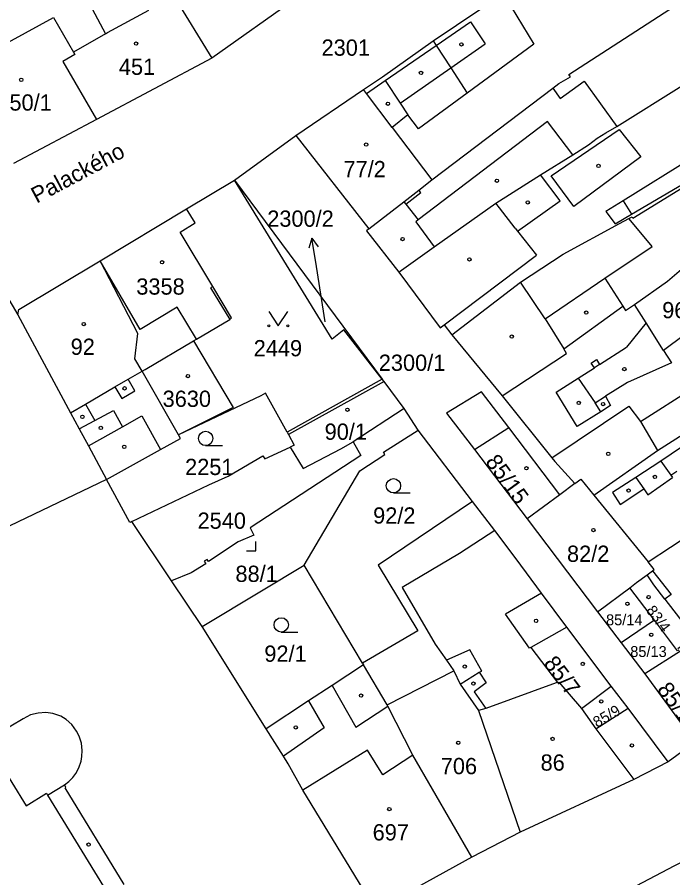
# Model space of a CAD drawing. Extents: x -679220 to -673243, y -1075091 to -1066557.
# Drawn here: x -676489.3 to -676420.8, y -1071759.5 to -1071669.5 of the extents above; entities that cross this region are included whole.
import ezdxf

# ---------------------------------------------------------------- set-up
doc = ezdxf.new("R2010")
doc.units = 0
for name, color, linetype in [('Hranice parcel', 7, 'Continuous'), ('Parcelní čísla', 7, 'Continuous'), ('Pop  PČ popisy', 7, 'Continuous'), ('Vnitřní kresba', 7, 'Continuous'), ('Značky budov', 7, 'Continuous'), ('Značky kultur', 7, 'Continuous')]:
    doc.layers.add(name, color=color, linetype=linetype)

msp = doc.modelspace()

# ---------------------------------------------------------------- linework, layer by layer
at = {"layer": 'Hranice parcel'}
for p, q in [((-676457.54, -1071665.6), (-676468.99, -1071673.74)), ((-676468.99, -1071673.74), (-676481.03, -1071680.16)), ((-676481.03, -1071680.16), (-676489.69, -1071684.74)), ((-676466.62, -1071686.49), (-676460.2, -1071681.83)), ((-676460.2, -1071681.83), (-676452.56, -1071691.6)), ((-676471.63, -1071689.48), (-676466.62, -1071686.49)), ((-676466.62, -1071686.49), (-676451.16, -1071707.32)), ((-676496.58, -1071688.3), (-676489.24, -1071700.57)), ((-676480.65, -1071694.94), (-676471.63, -1071689.48)), ((-676443.91, -1071702.66), (-676438.62, -1071709.04)), ((-676472.46, -1071713.12), (-676476.27, -1071706.46)), ((-676451.16, -1071707.32), (-676461.12, -1071712.84)), ((-676448.89, -1071710.38), (-676454.22, -1071713.88)), ((-676447.41, -1071712.65), (-676448.89, -1071710.38)), ((-676441.73, -1071720.1), (-676447.41, -1071712.65)), ((-676479.98, -1071717.8), (-676490.96, -1071723.08)), ((-676431.05, -1071718.24), (-676432.6, -1071719.4)), ((-676432.6, -1071719.4), (-676436.03, -1071721.91)), ((-676429.04, -1071719.44), (-676423.39, -1071726.4)), ((-676439.41, -1071723.14), (-676441.73, -1071720.1)), ((-676436.03, -1071721.91), (-676428.68, -1071731.63)), ((-676423.39, -1071726.4), (-676416.55, -1071721.95)), ((-676473.2, -1071728.4), (-676477.35, -1071722.21)), ((-676453.24, -1071737.03), (-676459.33, -1071726.76)), ((-676422.92, -1071727.36), (-676420.97, -1071729.84)), ((-676469.99, -1071733.18), (-676473.2, -1071728.4)), ((-676428.68, -1071731.63), (-676425.31, -1071729.15)), ((-676422.7, -1071732.52), (-676425.31, -1071729.15)), ((-676428.68, -1071731.63), (-676426.21, -1071734.89)), ((-676422.7, -1071732.52), (-676426.21, -1071734.89)), ((-676463.3, -1071743.87), (-676469.99, -1071733.18)), ((-676427.23, -1071739.43), (-676431.88, -1071733.26)), ((-676426.21, -1071734.89), (-676423.74, -1071738.14)), ((-676420, -1071735.76), (-676423.74, -1071738.14)), ((-676453.24, -1071737.03), (-676453.14, -1071737.2)), ((-676430.35, -1071741.77), (-676427.23, -1071739.43)), ((-676425.48, -1071741.71), (-676427.23, -1071739.43)), ((-676421.27, -1071747.32), (-676425.48, -1071741.71)), ((-676418.96, -1071745.63), (-676421.27, -1071747.32)), ((-676436.77, -1071754.7), (-676441.8, -1071757.31))]:
    msp.add_line(p, q, dxfattribs=at)
for points in [[(-676445.83, -1071671.91), (-676438.53, -1071666.96), (-676428.58, -1071660.59), (-676428.65, -1071660.49), (-676422.55, -1071656.64), (-676422.48, -1071656.74), (-676416.58, -1071652.94), (-676410.37, -1071648.97)], [(-676445.98, -1071686.46), (-676433.35, -1071676.88), (-676432.72, -1071676.4), (-676431.51, -1071675.68), (-676431.67, -1071675.43), (-676411.26, -1071662.18), (-676404.88, -1071658.28)], [(-676484.8, -1071662.19), (-676483.34, -1071664.69), (-676483.56, -1071664.81), (-676482.57, -1071666.51), (-676480.1, -1071671.18), (-676483.43, -1071673.12), (-676483.3, -1071673.35), (-676484.55, -1071674.07), (-676481.03, -1071680.16)], [(-676475.33, -1071663.38), (-676472.93, -1071667.3), (-676468.99, -1071673.74)], [(-676449.45, -1071696.12), (-676449.16, -1071695.9), (-676445.73, -1071693.47), (-676439.3, -1071688.9), (-676434.63, -1071685.95), (-676431.25, -1071683.83), (-676429.61, -1071682.8), (-676428.7, -1071682.09), (-676427.79, -1071681.54), (-676426.64, -1071680.89), (-676419.86, -1071676.64), (-676407.57, -1071668.83), (-676400.92, -1071664.77)], [(-676443.91, -1071702.66), (-676436.71, -1071697.18), (-676432.26, -1071694.25), (-676426.37, -1071691.03), (-676425.39, -1071690.51), (-676425.06, -1071690.34), (-676424.98, -1071690.46), (-676415.31, -1071684.52), (-676413.94, -1071683.68), (-676414.36, -1071683.06), (-676403.27, -1071675.59), (-676403.19, -1071675.52), (-676396.92, -1071671.69)], [(-676460.2, -1071681.83), (-676453.12, -1071677), (-676451.13, -1071675.67), (-676445.83, -1071671.91)], [(-676445.83, -1071671.91), (-676445.52, -1071672.4), (-676444.01, -1071674.75), (-676442.31, -1071677.4), (-676447.38, -1071681.13), (-676448.5, -1071679.66), (-676450.13, -1071680.97), (-676445.98, -1071686.46)], [(-676451.16, -1071707.32), (-676455.19, -1071702.14), (-676456.4, -1071703.12), (-676466.62, -1071686.49)], [(-676452.56, -1071691.6), (-676448.91, -1071688.75), (-676447.35, -1071687.53), (-676445.98, -1071686.46)], [(-676470.9, -1071703.29), (-676470.58, -1071703.11), (-676467.11, -1071701.07), (-676466.91, -1071700.9), (-676468.87, -1071697.6), (-676472.3, -1071691.92), (-676470.73, -1071690.97), (-676471.63, -1071689.48)], [(-676452.56, -1071691.6), (-676452.8, -1071691.79), (-676449.45, -1071696.12)], [(-676429.04, -1071719.44), (-676422.39, -1071714.77), (-676415, -1071710.08), (-676414.9, -1071710.24), (-676413.31, -1071709.22), (-676409.79, -1071707.02), (-676385.21, -1071692.07)], [(-676489.24, -1071700.57), (-676489.13, -1071700.02), (-676480.65, -1071694.94)], [(-676476.27, -1071706.46), (-676477.01, -1071705.17), (-676476.71, -1071702.54), (-676480.65, -1071694.94)], [(-676424.82, -1071699.49), (-676421.37, -1071697.06), (-676419.9, -1071695.81), (-676417.9, -1071694.39)], [(-676417.9, -1071694.39), (-676415.17, -1071698.64), (-676417.67, -1071700.59), (-676417.39, -1071701.04), (-676421.76, -1071704.3), (-676423.6, -1071701.41), (-676424.82, -1071699.49)], [(-676449.45, -1071696.12), (-676445.13, -1071701.95), (-676444.71, -1071701.63), (-676443.91, -1071702.66)], [(-676438.62, -1071709.04), (-676431.9, -1071704.62), (-676432.19, -1071704.15), (-676426.03, -1071699.66), (-676425.73, -1071700.13), (-676424.82, -1071699.49)], [(-676489.24, -1071700.57), (-676483.74, -1071710.83), (-676482.84, -1071712.5), (-676481.87, -1071714.29), (-676479.98, -1071717.8)], [(-676476.27, -1071706.46), (-676475.93, -1071706.3), (-676470.9, -1071703.29)], [(-676470.9, -1071703.29), (-676466.76, -1071710.26), (-676472.46, -1071713.12)], [(-676448.89, -1071710.38), (-676450.98, -1071707.56), (-676451.16, -1071707.32)], [(-676432.6, -1071719.4), (-676437.95, -1071712.38), (-676440.81, -1071708.65), (-676444.45, -1071710.86), (-676441.53, -1071714.68), (-676436.03, -1071721.91)], [(-676461.12, -1071712.84), (-676463.38, -1071708.79), (-676463.87, -1071709.07), (-676472.46, -1071713.12)], [(-676438.62, -1071709.04), (-676433.45, -1071715.53), (-676433.13, -1071715.93), (-676431.05, -1071718.24)], [(-676479.98, -1071717.8), (-676474.34, -1071714.68), (-676472.24, -1071713.51), (-676472.46, -1071713.12)], [(-676461.12, -1071712.84), (-676460.98, -1071713.1), (-676460.36, -1071714.22), (-676460.78, -1071714.41)], [(-676459.33, -1071726.76), (-676453.51, -1071716.89), (-676450.88, -1071715.18), (-676451.02, -1071714.94), (-676447.41, -1071712.65)], [(-676454.22, -1071713.88), (-676453.39, -1071715.28), (-676464.98, -1071722.87), (-676464.59, -1071723.61), (-676466.21, -1071724.31), (-676469.32, -1071726.37), (-676469.45, -1071726.17), (-676469.79, -1071726.33), (-676469.62, -1071726.63), (-676471.14, -1071727.57), (-676473.2, -1071728.4)], [(-676460.78, -1071714.41), (-676459.43, -1071716.64), (-676455.5, -1071714.61), (-676454.22, -1071713.88)], [(-676477.35, -1071722.21), (-676469.29, -1071718.36), (-676467.28, -1071717.45), (-676463.64, -1071715.33), (-676463.45, -1071715.63), (-676460.78, -1071714.41)], [(-676477.35, -1071722.21), (-676477.54, -1071722.31), (-676479.98, -1071717.8)], [(-676431.05, -1071718.24), (-676430.4, -1071717.77), (-676429.04, -1071719.44)], [(-676441.73, -1071720.1), (-676451.61, -1071726.76), (-676447.46, -1071733.65), (-676453.24, -1071737.03)], [(-676439.41, -1071723.14), (-676443.09, -1071725.53), (-676449.07, -1071729.1), (-676445.64, -1071735.04), (-676444.46, -1071736.7), (-676443.67, -1071737.81), (-676443.02, -1071739.21), (-676441.11, -1071741.95), (-676436.77, -1071754.7)], [(-676431.88, -1071733.26), (-676434.53, -1071729.68), (-676437.18, -1071726.1), (-676439.41, -1071723.14)], [(-676422.92, -1071727.36), (-676422.74, -1071727.23), (-676423.39, -1071726.4)], [(-676469.99, -1071733.18), (-676463.8, -1071729.44), (-676459.33, -1071726.76)], [(-676425.31, -1071729.15), (-676424.6, -1071728.59), (-676423.48, -1071727.78), (-676422.92, -1071727.36)], [(-676420.97, -1071729.84), (-676421.63, -1071730.33), (-676418.58, -1071734.3), (-676420.26, -1071735.53)], [(-676420.18, -1071735.64), (-676420.3, -1071735.72), (-676422.7, -1071732.52)], [(-676431.88, -1071733.26), (-676435.63, -1071735.39), (-676432.84, -1071739.04), (-676432.71, -1071738.99), (-676430.35, -1071741.77)], [(-676453.14, -1071737.2), (-676456.4, -1071739.34), (-676458.86, -1071740.95), (-676463.3, -1071743.87)], [(-676441.8, -1071757.31), (-676447.98, -1071746.65), (-676450.58, -1071741.53), (-676450.65, -1071741.39), (-676453.14, -1071737.2)], [(-676423.74, -1071738.14), (-676418.87, -1071744.77), (-676419.3, -1071745.06), (-676418.96, -1071745.63)], [(-676430.35, -1071741.77), (-676428.83, -1071743.89), (-676425.48, -1071741.71)], [(-676478.14, -1071760.18), (-676484.32, -1071750.06), (-676484.23, -1071750), (-676484.39, -1071749.75), (-676483.92, -1071749.39), (-676483.51, -1071748.97), (-676483.19, -1071748.55), (-676482.89, -1071747.98), (-676482.64, -1071747.27), (-676482.55, -1071746.77), (-676482.53, -1071746.15), (-676482.6, -1071745.39), (-676482.85, -1071744.66), (-676483.11, -1071744.12), (-676483.61, -1071743.44), (-676484.2, -1071742.91), (-676484.77, -1071742.57), (-676485.59, -1071742.28), (-676486.33, -1071742.18), (-676487.11, -1071742.23), (-676487.94, -1071742.43), (-676488.69, -1071742.85), (-676492.58, -1071745.13)], [(-676453.16, -1071760.64), (-676459.47, -1071750.3), (-676461.01, -1071747.53), (-676461.5, -1071746.75), (-676463.3, -1071743.87)], [(-676421.27, -1071747.32), (-676424.86, -1071749.18), (-676436.77, -1071754.7)], [(-676439.72, -1071768.25), (-676420.67, -1071758.23), (-676415.87, -1071755.76)], [(-676441.8, -1071757.31), (-676449.57, -1071761.6), (-676453.16, -1071760.64)]]:
    msp.add_lwpolyline(points, dxfattribs=at)
at = {"layer": 'Pop  PČ popisy'}
for p, q in [((-676458.509, -1071692.546), (-676458.847, -1071693.613)), ((-676458.04, -1071695.51), (-676458.509, -1071692.546)), ((-676458.509, -1071692.546), (-676457.858, -1071693.457)), ((-676457.14, -1071701.31), (-676458.04, -1071695.51))]:
    msp.add_line(p, q, dxfattribs=at)
at = {"layer": 'Vnitřní kresba'}
for p, q in [((-676438.53, -1071666.96), (-676435.32, -1071672.27)), ((-676479.88, -1071671.06), (-676475.55, -1071668.72)), ((-676495.76, -1071675.07), (-676485.54, -1071669.48)), ((-676485.54, -1071669.48), (-676483.43, -1071673.12)), ((-676445.52, -1071672.4), (-676441.93, -1071669.92)), ((-676441.93, -1071669.92), (-676440.42, -1071672.25)), ((-676480.1, -1071671.18), (-676479.88, -1071671.06)), ((-676450.85, -1071676.08), (-676445.52, -1071672.4)), ((-676444.01, -1071674.75), (-676440.42, -1071672.25)), ((-676435.32, -1071672.27), (-676442.31, -1071677.4)), ((-676449.3, -1071678.44), (-676444.01, -1071674.75)), ((-676452.8, -1071677.43), (-676450.85, -1071676.08)), ((-676450.85, -1071676.08), (-676449.3, -1071678.44)), ((-676432.58, -1071677.96), (-676430.06, -1071676.14)), ((-676430.06, -1071676.14), (-676426.64, -1071680.89)), ((-676452.8, -1071677.43), (-676453.12, -1071677)), ((-676433.35, -1071676.88), (-676432.58, -1071677.96)), ((-676450.13, -1071680.97), (-676452.8, -1071677.43)), ((-676449.3, -1071678.44), (-676448.5, -1071679.66)), ((-676433.89, -1071680.36), (-676447.43, -1071690.66)), ((-676431.25, -1071683.83), (-676433.89, -1071680.36)), ((-676433.53, -1071686.03), (-676426.4, -1071681.2)), ((-676426.4, -1071681.2), (-676424.16, -1071684.05)), ((-676416.39, -1071682.66), (-676426, -1071688.65)), ((-676424.16, -1071684.05), (-676431.13, -1071689.25)), ((-676425.13, -1071690.06), (-676415.41, -1071684.35)), ((-676432.58, -1071688.67), (-676434.63, -1071685.95)), ((-676431.13, -1071689.25), (-676433.53, -1071686.03)), ((-676448.71, -1071689), (-676447.15, -1071687.78)), ((-676447.15, -1071687.78), (-676447.35, -1071687.53)), ((-676448.91, -1071688.75), (-676448.71, -1071689)), ((-676437.02, -1071691.83), (-676432.58, -1071688.67)), ((-676426, -1071688.65), (-676427.8, -1071689.77)), ((-676426, -1071688.65), (-676425.13, -1071690.06)), ((-676448.71, -1071689), (-676447.43, -1071690.66)), ((-676438.91, -1071689.4), (-676439.3, -1071688.9)), ((-676437.26, -1071691.52), (-676438.91, -1071689.4)), ((-676427.8, -1071689.77), (-676426.84, -1071691.06)), ((-676447.43, -1071690.66), (-676447.66, -1071690.84)), ((-676426.84, -1071691.06), (-676425.13, -1071690.06)), ((-676425.02, -1071690.96), (-676425.39, -1071690.51)), ((-676447.66, -1071690.84), (-676445.73, -1071693.47)), ((-676437.26, -1071691.52), (-676437.02, -1071691.83)), ((-676422.95, -1071693.44), (-676425.02, -1071690.96)), ((-676437.02, -1071691.83), (-676435.06, -1071694.35)), ((-676427.89, -1071696.76), (-676422.95, -1071693.44)), ((-676476.45, -1071702.11), (-676480.65, -1071694.94)), ((-676444.71, -1071701.63), (-676435.06, -1071694.35)), ((-676434.14, -1071701), (-676427.89, -1071696.76)), ((-676427.89, -1071696.76), (-676426.03, -1071699.66)), ((-676468.87, -1071697.6), (-676469.1, -1071697.74)), ((-676469.1, -1071697.74), (-676467.11, -1071701.07)), ((-676434.14, -1071701), (-676436.71, -1071697.18)), ((-676472.59, -1071699.78), (-676476.45, -1071702.11)), ((-676470.58, -1071703.11), (-676472.59, -1071699.78)), ((-676434.14, -1071701), (-676432.19, -1071704.15)), ((-676423.6, -1071701.41), (-676425.63, -1071703.98)), ((-676428.45, -1071705.78), (-676425.63, -1071703.98)), ((-676421.76, -1071704.3), (-676420.93, -1071705.59)), ((-676429.32, -1071705.62), (-676428.77, -1071705.27)), ((-676429, -1071706.13), (-676429.32, -1071705.62)), ((-676428.45, -1071705.78), (-676429, -1071706.13)), ((-676428.77, -1071705.27), (-676428.45, -1071705.78)), ((-676420.93, -1071705.59), (-676425.54, -1071707.65)), ((-676477.73, -1071707.31), (-676476.27, -1071706.46)), ((-676430.68, -1071707.2), (-676429, -1071706.13)), ((-676424.17, -1071711.73), (-676415.28, -1071706.05)), ((-676479.1, -1071708.12), (-676477.73, -1071707.31)), ((-676477.03, -1071708.52), (-676477.73, -1071707.31)), ((-676450.98, -1071707.56), (-676460.98, -1071713.1)), ((-676433, -1071708.68), (-676430.68, -1071707.2)), ((-676430.68, -1071707.2), (-676428.93, -1071709.78)), ((-676425.54, -1071707.65), (-676427.83, -1071709.09)), ((-676482.19, -1071709.93), (-676479.1, -1071708.12)), ((-676479.1, -1071708.12), (-676478.4, -1071709.32)), ((-676478.4, -1071709.32), (-676477.03, -1071708.52)), ((-676430.8, -1071712.26), (-676433, -1071708.68)), ((-676428.93, -1071709.78), (-676427.83, -1071709.09)), ((-676427.83, -1071709.09), (-676427.32, -1071710.07)), ((-676483.74, -1071710.83), (-676482.19, -1071709.93)), ((-676482.19, -1071709.93), (-676481.2, -1071711.63)), ((-676433.45, -1071715.53), (-676425.39, -1071710.14)), ((-676428.34, -1071710.71), (-676428.93, -1071709.78)), ((-676427.32, -1071710.07), (-676428.34, -1071710.71)), ((-676425.39, -1071710.14), (-676424.17, -1071711.73)), ((-676481.2, -1071711.63), (-676479.25, -1071710.58)), ((-676479.25, -1071710.58), (-676478.3, -1071712.28)), ((-676478.3, -1071712.28), (-676476.29, -1071711.15)), ((-676476.29, -1071711.15), (-676474.34, -1071714.68)), ((-676428.34, -1071710.71), (-676430.8, -1071712.26)), ((-676414.54, -1071710.8), (-676422.04, -1071715.88)), ((-676482.84, -1071712.5), (-676481.2, -1071711.63)), ((-676481.87, -1071714.29), (-676478.3, -1071712.28)), ((-676424.17, -1071711.73), (-676422.39, -1071714.77)), ((-676441.53, -1071714.68), (-676437.95, -1071712.38)), ((-676422.04, -1071715.88), (-676424.68, -1071717.6)), ((-676422.04, -1071715.88), (-676421.01, -1071717.35)), ((-676424.68, -1071717.6), (-676427.1, -1071719.18)), ((-676424.68, -1071717.6), (-676423.84, -1071718.79)), ((-676423.41, -1071719.41), (-676420.83, -1071717.61)), ((-676421.01, -1071717.35), (-676420.37, -1071716.95)), ((-676421.01, -1071717.35), (-676420.83, -1071717.61)), ((-676427.1, -1071719.18), (-676426.29, -1071720.42)), ((-676426.29, -1071720.42), (-676423.84, -1071718.79)), ((-676423.84, -1071718.79), (-676423.41, -1071719.41)), ((-676422.79, -1071728.81), (-676423.48, -1071727.78)), ((-676421.63, -1071730.33), (-676422.79, -1071728.81)), ((-676434.53, -1071729.68), (-676438.29, -1071731.88)), ((-676435.77, -1071735.45), (-676438.29, -1071731.88)), ((-676442.01, -1071735.62), (-676444.46, -1071736.7)), ((-676440.75, -1071737.84), (-676442.01, -1071735.62)), ((-676435.63, -1071735.39), (-676435.77, -1071735.45)), ((-676450.65, -1071741.39), (-676443.67, -1071737.81)), ((-676443.02, -1071739.21), (-676441.05, -1071737.96)), ((-676441.05, -1071737.96), (-676440.75, -1071737.84)), ((-676441.05, -1071737.96), (-676440.29, -1071739.09)), ((-676440.29, -1071739.09), (-676441.57, -1071740.02)), ((-676432.99, -1071739.09), (-676440.34, -1071741.76)), ((-676432.84, -1071739.04), (-676432.99, -1071739.09)), ((-676456.4, -1071739.34), (-676453.94, -1071743.7)), ((-676441.57, -1071740.02), (-676440.34, -1071741.76)), ((-676458.86, -1071740.95), (-676457.24, -1071743.79)), ((-676453.94, -1071743.7), (-676450.58, -1071741.53)), ((-676440.34, -1071741.76), (-676441.11, -1071741.95)), ((-676457.24, -1071743.79), (-676461.5, -1071746.75)), ((-676428.83, -1071743.89), (-676424.86, -1071749.18)), ((-676492.58, -1071745.13), (-676488.37, -1071751.93)), ((-676452.72, -1071746.11), (-676459.47, -1071750.3)), ((-676451.11, -1071748.71), (-676452.72, -1071746.11)), ((-676447.98, -1071746.65), (-676451.11, -1071748.71)), ((-676486.14, -1071750.82), (-676484.39, -1071749.75)), ((-676488.37, -1071751.93), (-676486.26, -1071750.62)), ((-676486.26, -1071750.62), (-676486.14, -1071750.82)), ((-676486.14, -1071750.82), (-676479.65, -1071761.45))]:
    msp.add_line(p, q, dxfattribs=at)
at = {"layer": 'Značky budov'}
for centre in [(-676476.897, -1071672.209), (-676442.887, -1071672.289), (-676447.117, -1071675.279), (-676488.897, -1071675.999), (-676450.577, -1071678.499), (-676452.847, -1071682.769), (-676428.567, -1071684.999), (-676439.177, -1071686.559), (-676435.957, -1071688.829), (-676449.047, -1071692.659), (-676474.177, -1071695.079), (-676442.057, -1071694.789), (-676429.847, -1071700.339), (-676482.367, -1071701.549), (-676437.637, -1071702.849), (-676471.477, -1071706.989), (-676425.867, -1071706.259), (-676478.097, -1071708.269), (-676454.807, -1071710.509), (-676430.627, -1071709.799), (-676428.087, -1071709.919), (-676482.507, -1071711.249), (-676480.577, -1071712.409), (-676478.127, -1071714.389), (-676427.547, -1071715.119), (-676436.107, -1071716.629), (-676422.677, -1071717.529), (-676425.427, -1071718.959), (-676429.097, -1071723.099), (-676423.337, -1071730.099), (-676425.547, -1071730.799), (-676435.097, -1071732.589), (-676423.057, -1071734.049), (-676442.547, -1071737.379), (-676430.207, -1071737.089), (-676441.647, -1071739.149), (-676453.377, -1071740.409), (-676428.277, -1071741.009), (-676460.207, -1071743.739), (-676443.217, -1071745.339), (-676433.367, -1071744.939), (-676425.067, -1071745.619), (-676450.427, -1071752.279), (-676481.857, -1071755.999)]:
    msp.add_circle(centre, 0.175, dxfattribs=at)
at = {"layer": 'Značky kultur'}
for p, q in [((-676469.623, -1071714.26), (-676467.873, -1071714.26)), ((-676449.993, -1071719.21), (-676448.243, -1071719.21)), ((-676464.37, -1071725.28), (-676464.37, -1071724.28)), ((-676465.371, -1071725.28), (-676464.37, -1071725.28)), ((-676461.723, -1071733.76), (-676459.973, -1071733.76))]:
    msp.add_line(p, q, dxfattribs=at)
msp.add_lwpolyline([(-676463.03, -1071700.229), (-676462.03, -1071701.73), (-676461.03, -1071700.229)], dxfattribs=at)
for centre, radius in [((-676463.03, -1071701.729), 0.1), ((-676461.03, -1071701.729), 0.1), ((-676469.623, -1071713.51), 0.75), ((-676449.993, -1071718.46), 0.75), ((-676461.723, -1071733.01), 0.75)]:
    msp.add_circle(centre, radius, dxfattribs=at)

# ---------------------------------------------------------------- texts
at = {"layer": 'Parcelní čísla'}
for s, height, p in [('2301', 1.7, (-676457.51, -1071673.479)), ('451', 1.7, (-676478.69, -1071675.479)), ('450/1', 1.7, (-676491.39, -1071679.22)), ('77/2', 1.7, (-676455.22, -1071686.19)), ('2300/2', 1.7, (-676463.185, -1071691.37)), ('3358', 1.7, (-676476.87, -1071698.47)), ('96/1', 1.7, (-676421.91, -1071700.94)), ('92', 1.7, (-676483.73, -1071704.769)), ('2449', 1.7, (-676464.6, -1071704.92)), ('2300/1', 1.7, (-676451.53, -1071706.44)), ('3630', 1.7, (-676474.12, -1071710.21)), ('90/1', 1.7, (-676457.19, -1071713.65)), ('2251', 1.7, (-676471.77, -1071717.34)), ('2540', 1.7, (-676470.47, -1071722.96)), ('92/2', 1.7, (-676452.12, -1071722.42)), ('82/2', 1.7, (-676431.86, -1071726.42)), ('88/1', 1.7, (-676466.51, -1071728.519)), ('85/14', 1.14, (-676427.78, -1071733.05)), ('92/1', 1.7, (-676463.49, -1071736.87)), ('85/13', 1.14, (-676425.25, -1071736.37)), ('706', 1.7, (-676445.05, -1071748.63)), ('86', 1.7, (-676434.62, -1071748.259)), ('697', 1.7, (-676452.17, -1071755.56))]:
    msp.add_text(s, height=height, dxfattribs=at).set_placement(p)
for s, height, rotation, p in [('85/15', 1.7, 306, (-676440.457, -1071715.959)), ('83/4', 1.139, 307, (-676423.653, -1071731.515)), ('85/7', 1.7, 307, (-676434.378, -1071737.061)), ('85/11', 1.7, 306, (-676422.517, -1071739.779)), ('85/9', 1.14, 30, (-676428.725, -1071743.793))]:
    msp.add_text(s, height=height, rotation=rotation, dxfattribs=at).set_placement(p)
at = {"layer": 'Pop  PČ popisy'}
msp.add_text('Palackého', height=1.7, rotation=28, dxfattribs=at).set_placement((-676487.283, -1071688.967))

doc.saveas('drawing.dxf')
